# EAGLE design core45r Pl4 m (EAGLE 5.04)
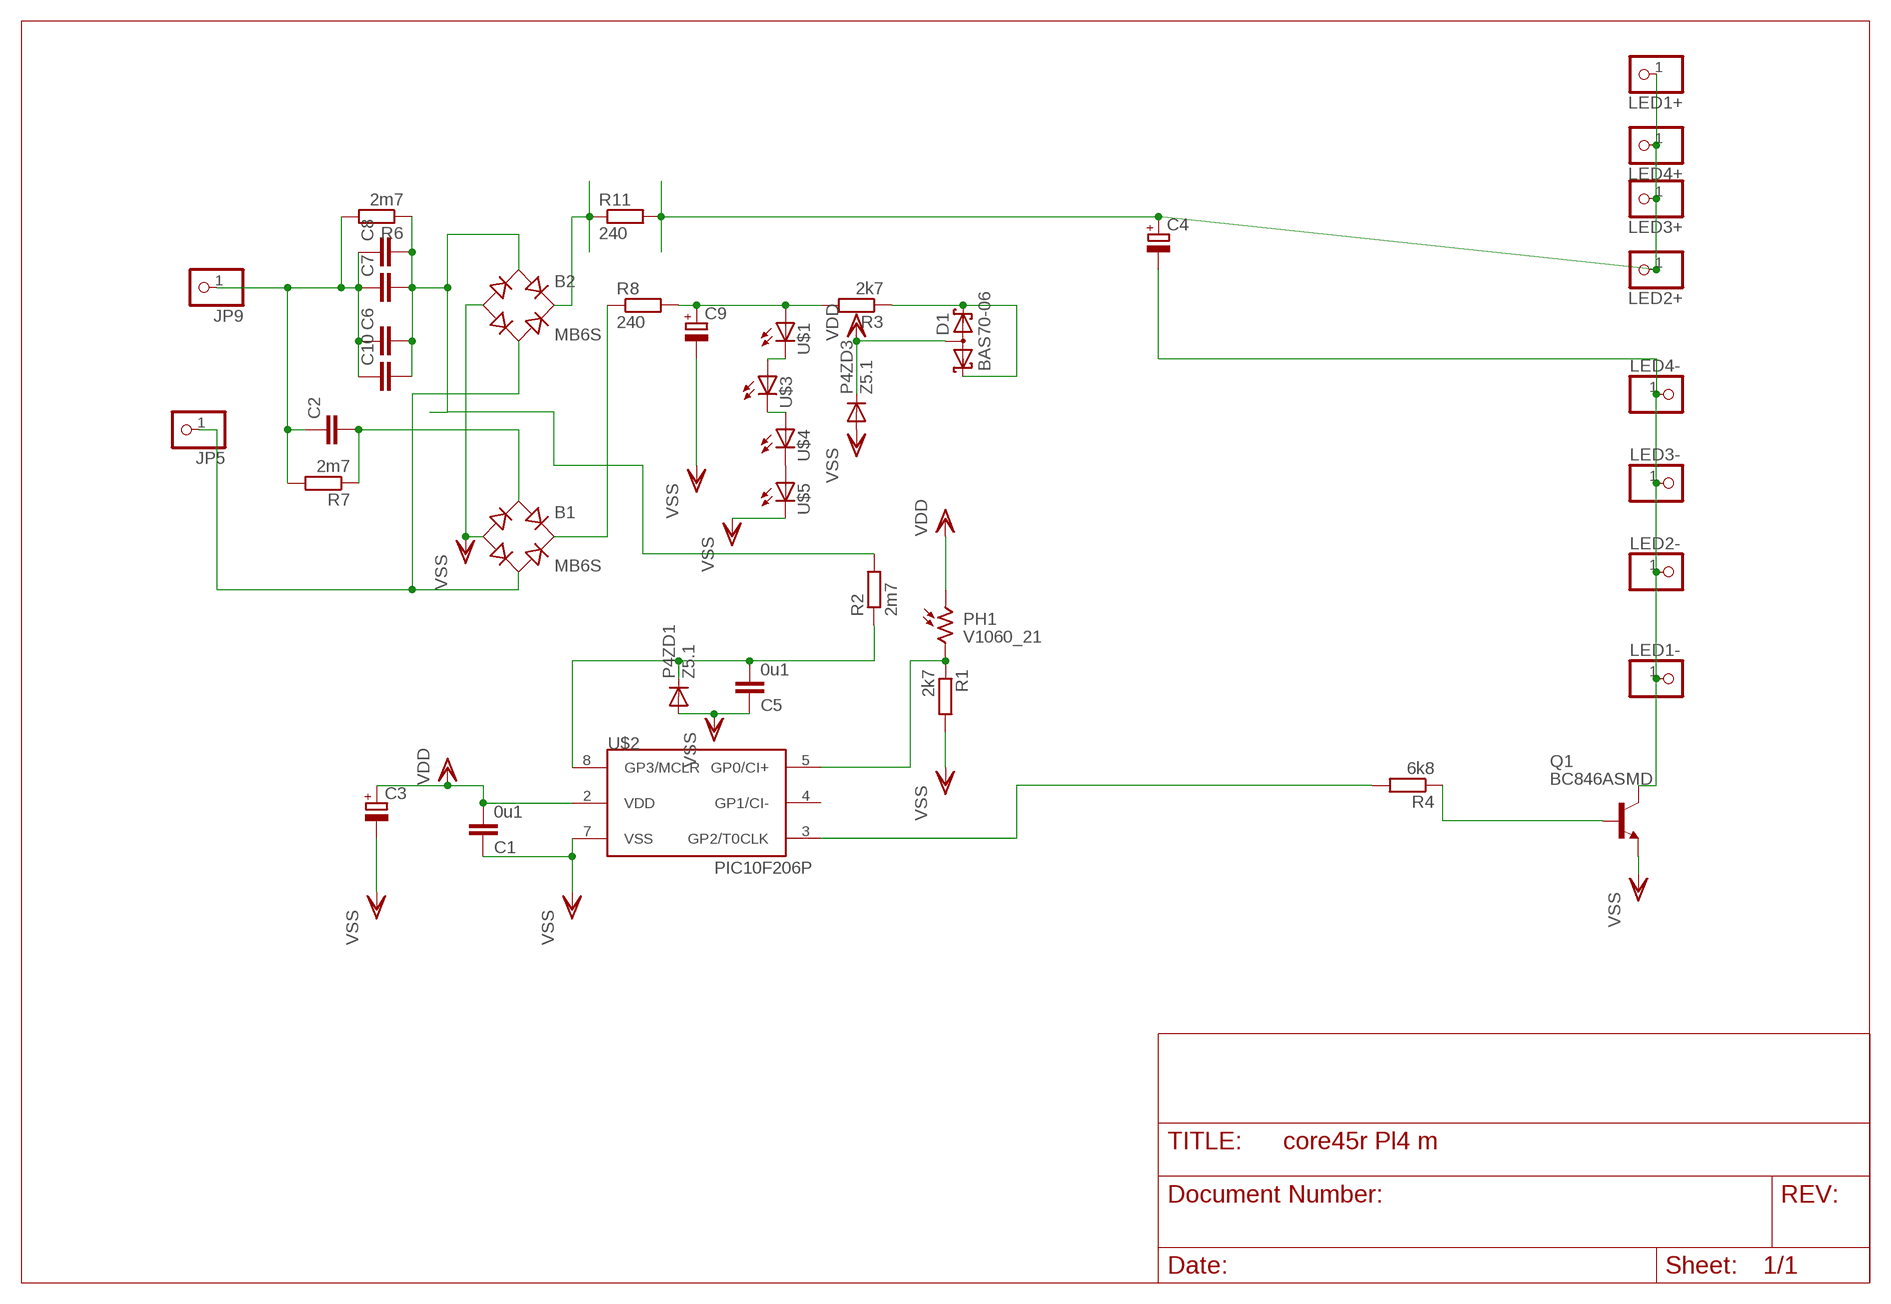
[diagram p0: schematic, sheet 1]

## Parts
B1  MB6S  [SOIC-4]
B2  MB6S  [SOIC-4]
C1  0u1  C-EUC1206  [C1206]
C2  C-EU075-052X106  [C075-052X106]
C3  CPOL-EU5-13  [2,5-5-FLAT]
C4  CPOL-EUTT5D11L  [TT5D11L]
C5  0u1  C-EUC1206  [C1206]
C6  C-EU150-064X183  [C150-064X183]
C7  C-EU150-054X183  [C150-054X183]
C8  C-EU150-054X183  [C150-054X183]
C9  CPOL-EUTT5D11L  [TT5D11L]
C10  C-EU150-064X183  [C150-064X183]
D1  BAS70-06  [SOT23]
JP5  PINHD-1X1  [1X01]
JP9  PINHD-1X1  [1X01]
LED1+  PINHD-1X1  [1X01]
LED1-  PINHD-1X1  [1X01]
LED2+  PINHD-1X1  [1X01]
LED2-  PINHD-1X1  [1X01]
LED3+  PINHD-1X1  [1X01]
LED3-  PINHD-1X1  [1X01]
LED4+  PINHD-1X1  [1X01]
LED4-  PINHD-1X1  [1X01]
P4ZD1  Z5.1  DIODE-MINIMELF  [MINIMELF]
P4ZD3  Z5.1  DIODE-MINIMELF  [MINIMELF]
PH1  V1060_21  [TO-5_V10]
Q1  BC846ASMD  [SOT23]
R1  2k7  R-EU_R0805  [R0805]
R2  2m7  R-EU_R1206  [R1206]
R3  2k7  R-EU_R0805  [R0805]
R4  6k8  R-EU_R1206  [R1206]
R6  2m7  R-EU_R1206  [R1206]
R7  2m7  R-EU_R1206  [R1206]
R8  240  R-EU_0204/5  [0204/5]
R11  240  R-EU_0204/7  [0204/7]
U$1  LED  [P-LCC4-MINI]
U$2  PIC10F206P  [DIL8]
U$3  LED  [P-LCC4-MINI]
U$4  LED  [P-LCC4-MINI]
U$5  LED  [P-LCC4-MINI]

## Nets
AC1: B1.~2(AC2) B2.~2(AC2) JP5.1
AC2: C2.1 C6.1 C7.1 C8.1 C10.1 JP9.1 R6.2 R7.2
CBIG: B2.~1(AC1) C6.2 C7.2 C8.2 C10.2 R2.2 R6.1
D+: C4.+ LED1+.1 LED2+.1 LED3+.1 LED4+.1 R11.2
D-: C4.- LED1-.1 LED2-.1 LED3-.1 LED4-.1 Q1.3(C)
DR+: C9.+ R3.2 R8.2 U$1.P$3(A)
N$1: C5.2 P4ZD1.C R2.1 U$2.8(GP3/MCLR)
N$2: U$4.P$1(C) U$5.P$3(A)
N$4: U$3.P$1(C) U$4.P$3(A)
N$5: D1.1(K1) D1.2(K2) R3.1
N$8: B1.~1(AC1) C2.2 R7.1
N$9: U$1.P$1(C) U$3.P$3(A)
N$11: B2.+ R11.1
N$12: Q1.1(B) R4.1
N$15: R4.2 U$2.3(GP2/T0CLK)
N$17: PH1.2 R1.1 U$2.5(GP0/CI+)
RECDR+: B1.+ R8.1
VDD: C1.2 C3.+ D1.3(AA) P4ZD3.C PH1.1 U$2.2(VDD)
VSS: B1.- B2.- C1.1 C3.- C5.1 C9.- P4ZD1.A P4ZD3.A Q1.2(E) R1.2 U$2.7(VSS) U$5.P$1(C)
Unconnected: U$2.4(GP1/CI-)

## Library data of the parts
B1 B2 = rectifier:MB*S: Bridge Rectifier Source: http://www.fairchildsemi.com/ds/MB/MB6S.pdf
C1 C5 = rcl:C-EU: CAPACITOR, European symbol
C2 C6-C8 C10 = rcl-2:C-EU: CAPACITOR, European symbol
C3 C4 C9 = rcl-2:CPOL-EU: POLARIZED CAPACITOR, European symbol
D1 = diode:BAS70-06: Silicon Schottky Diodes General-purpose diode for high-speed switching
JP5 JP9 LED1+ LED1- LED2+ LED2- LED3+ LED3- LED4+ LED4- = pinhead(2):PINHD-1X1: PIN HEADER
P4ZD1 P4ZD3 = diode:DIODE-: DIODE
PH1 = photo-elements:?1060*: Sensor Street Light control
Q1 = transistor-npn:BC846*: NPN Transistor
R1-R4 R6-R8 R11 = rcl-2:R-EU_: RESISTOR, European symbol
U$1 U$3-U$5 = led(2):LED: LED
U$2 = microchip-3:PIC10F2*: uPC nW 0,25/0,5k Program Flash memory Comparator

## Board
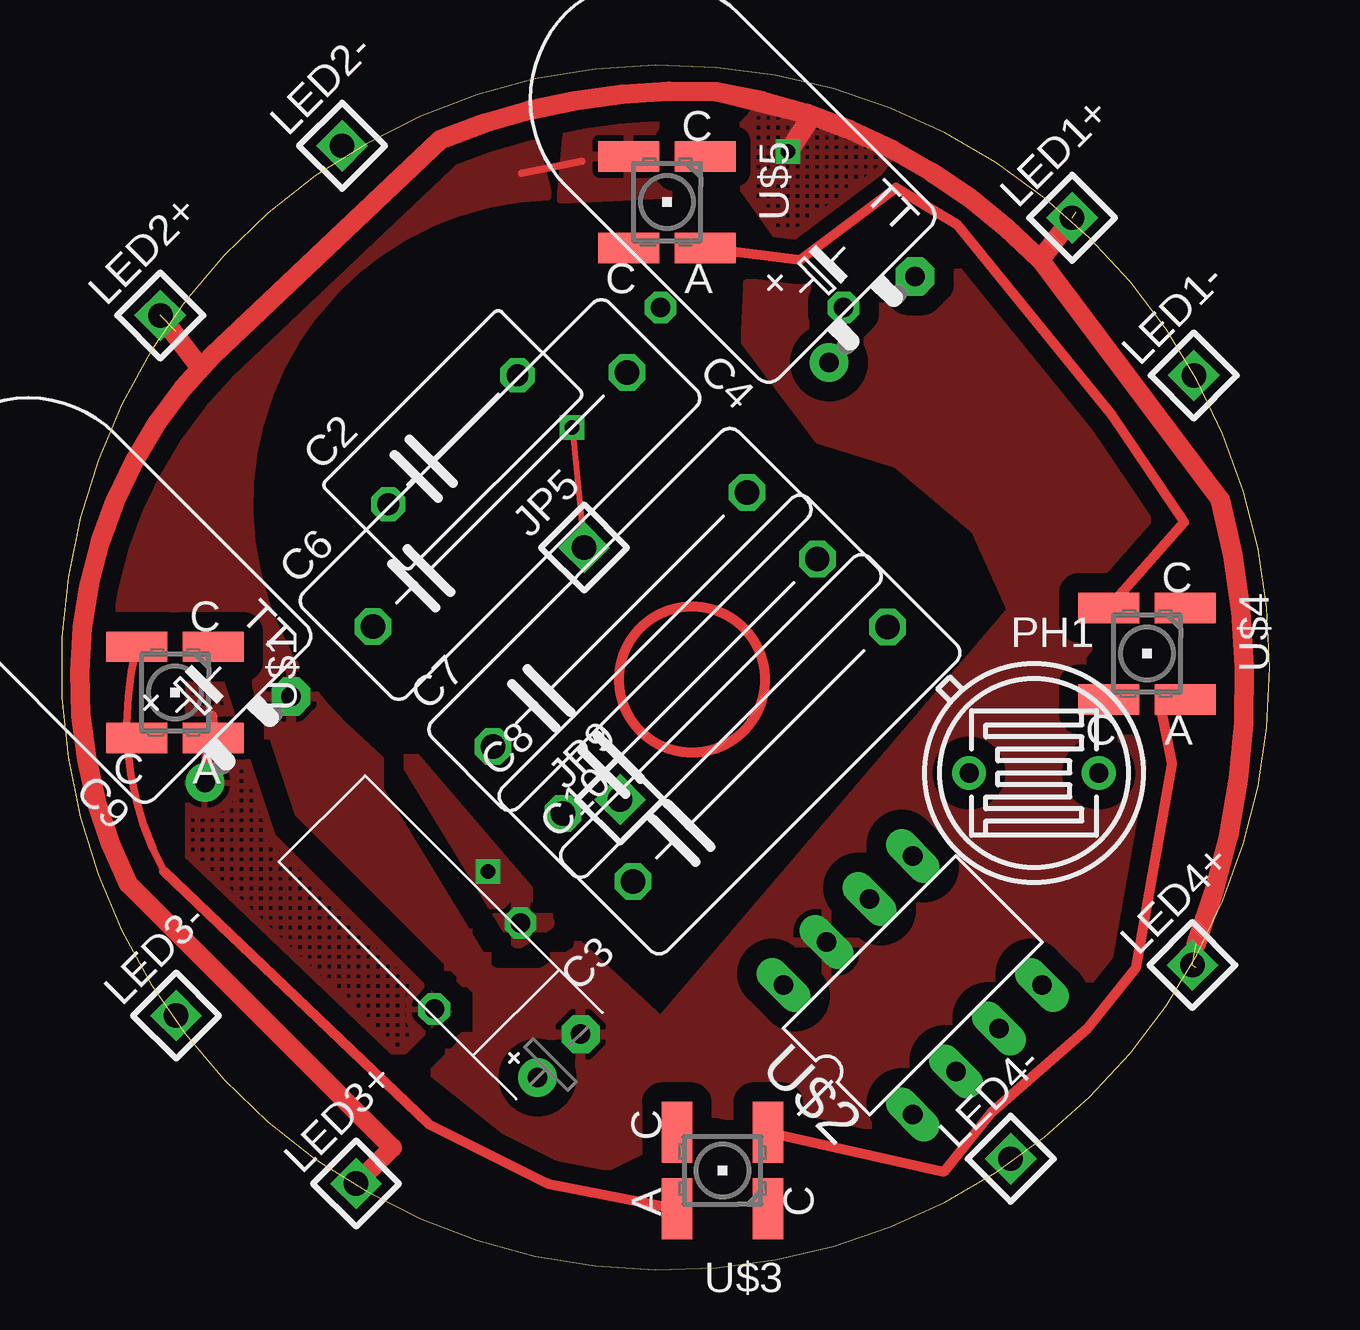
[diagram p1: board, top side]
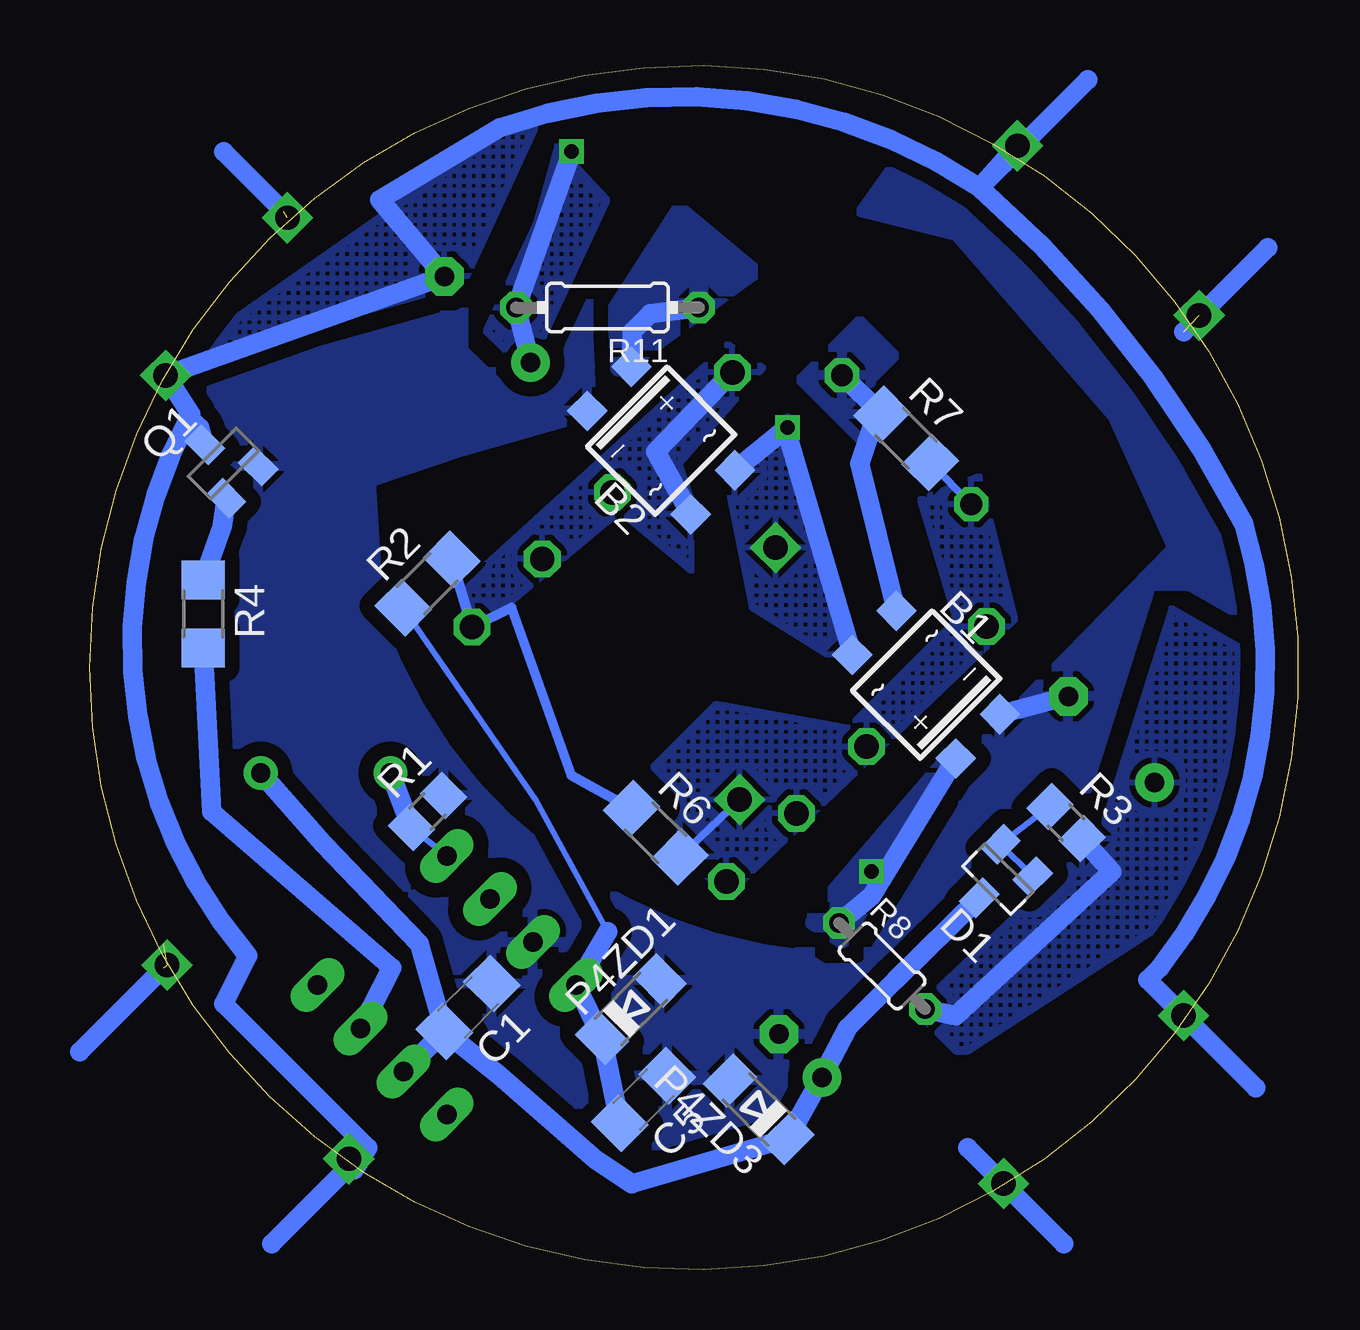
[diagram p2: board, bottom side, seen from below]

Size 50.33 x 50.19 mm. Coordinates in mm from the lower left corner, seen from the top.
Outline: 27.25,0.09 arc171 27.25,50.09 arc190 27.25,0.09
Copper layers (1*16): Top 0.035mm / dielectric 1.5mm / Bottom 0.035mm
Design rules "default": minimum track width 10mil, minimum drill 24mil, track to track 8mil, track to pad 8mil, pad to pad 8mil, via to via 8mil, smd to smd 8mil, copper to edge 40mil, drill to drill 8mil, minimum pad ring 10mil, minimum via ring 8mil, stop-mask expansion 4mil, vias tented up to drill 0mil, thermal gap 10mil

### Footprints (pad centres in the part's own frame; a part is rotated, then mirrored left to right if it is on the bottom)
SOIC-4 = smd 1.2 x 1.2: + 1.3,3.05; - -1.3,3.05; ~1 -1.3,-3.05; ~2 1.3,-3.05
C1206 = smd 1.6 x 1.8: 1 -1.4,0; 2 1.4,0
C075-052X106 = drill 0.914 octagon: 1 -3.81,0; 2 3.81,0
2,5-5-FLAT = drill 0.813 pad 1.6 round: + -1.27,0 | drill 0.813 pad 1.6 octagon: - 1.27,0
TT5D11L = drill 0.813 pad 1.6 round: + -2.54,0 | drill 0.813 pad 1.6 octagon: - 2.54,0
C150-064X183 = drill 1.016 octagon: 1 -7.493,0; 2 7.493,0
C150-054X183 = drill 1.016 octagon: 1 -7.493,0; 2 7.493,0
SOT23 = smd 1 x 1.4: 1 -0.95,-1.1; 2 0.95,-1.1; 3 0,1.1
1X01 = drill 1.016 square: 1 0,0
MINIMELF = smd 1.4 x 1.8: A 1.7,0; C -1.7,0
TO-5_V10 = drill 0.8 pad 1.4 round: 1 -2.7,0; 2 2.7,0
R0805 = smd 1.3 x 1.5: 1 -0.95,0; 2 0.95,0
R1206 = smd 1.6 x 1.803: 1 -1.422,0; 2 1.422,0
0204/5 = drill 0.813 octagon: 1 -2.54,0; 2 2.54,0
0204/7 = drill 0.813 octagon: 1 -3.81,0; 2 3.81,0
P-LCC4-MINI = smd 2.54 x 1.27: P$1 1.587,-1.905; P$2 -1.587,-1.905; P$3 -1.587,1.905; P$4 1.587,1.905
DIL8 = drill 0.813 long: 1 -3.81,-3.81; 2 -1.27,-3.81; 3 1.27,-3.81; 4 3.81,-3.81; 5 3.81,3.81; 6 1.27,3.81; 7 -1.27,3.81; 8 -3.81,3.81

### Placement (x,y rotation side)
B1  15.48,24.38 225 bottom
B2  26.52,34.55 45 bottom
C1  34.56,10.93 225 bottom
C2  16.29,34.58 45 top
C3  20.72,8.92 45 top
C4  33.75,39.59 45 top
C5  27.25,7.09 225 bottom
C6  18.25,32.09 45 top
C7  23.25,27.09 45 top
C8  26.17,24.32 45 top
C9  7.75,22.09 45 top
C10  29.1,21.48 45 top
D1  12.48,16.28 135 bottom
JP5  21.75,30.09 45 top
JP9  23.25,19.59 45 top
LED1+  42.09,43.83 45 top
LED1-  47.16,37.26 45 top
LED2+  4.1,39.76 45 top
LED2-  11.67,46.83 45 top
LED3+  12.25,3.59 45 top
LED3-  4.75,10.59 45 top
LED4+  47.1,12.69 45 top
LED4-  39.53,4.62 45 top
P4ZD1  27.78,10.86 45 bottom
P4ZD3  22.45,6.68 135 bottom
PH1  40.5,20.7 180 top
Q1  44.75,33.59 45 bottom
R1  36.25,19.09 45 bottom
R2  36.25,28.59 45 bottom
R3  9.65,18.63 315 bottom
R4  45.59,27.32 270 bottom
R6  26.75,18.21 315 bottom
R7  16.31,34.64 315 bottom
R8  17.31,12.66 315 bottom
R11  28.75,40.09 180 bottom
U$1  4.71,24.05 180 top
U$2  35.45,11.86 45 top
U$3  27.52,4.13 90 top
U$4  45.21,25.67 180 top
U$5  25.21,44.48 180 top

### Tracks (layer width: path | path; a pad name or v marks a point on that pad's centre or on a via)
AC1  (via drill 0.6)
  Top 0.254: v21.25,35.09 JP5.1
  Bottom 0.254: 21.32,35.05 v21.25,35.09
  Bottom 0.813: B1.~2 21.32,35.05 B2.~2
  pour Bottom (isolate 0.61, hatched): 21.25,35.59 23.75,32.59 22.75,27.59 18.75,25.09
AC2
  Bottom 0.305: R6.2 JP9.1 | C2.1 R7.2
  pour Bottom (isolate 0.813, rank 2, hatched): 13.25,33.09 15.75,32.09 14.25,27.09 18.75,22.59 24.25,23.59 28.25,19.59 23.75,15.59 11.75,27.09
CBIG
  Bottom 0.406: R6.1 30.25,20.59 32.75,27.59 C10.2 R2.2
  Bottom 0.813: B2.~1 26.75,34.09 C6.2
  pour Bottom (isolate 0.61, hatched): 23.75,38.59 34.75,28.59 34.25,26.59 28.25,31.59 25.25,29.09 25.25,32.09 25.75,33.59 22.25,37.59
D+  (via drill 0.6)  (4 unrouted)
  Top 0.406: 6.25,38.09 5.75,37.59
  Top 0.813: 5.75,37.59 LED2+.1 | LED3+.1 13.75,5.09 2.75,16.09 arc-71 6.25,38.09 15.75,47.09 arc-25 27.25,49.09 | 47.25,13.59 arc36 48.25,32.09 40.75,42.09 | 40.75,42.09 LED1+.1 | 27.25,49.09 arc-37 40.75,42.09 | v30.25,46.59 31.25,48.09 27.25,49.09
  Bottom 0.813: C4.+ R11.2 v30.25,46.59 | 42.25,44.09 44.75,46.59 | 47.25,12.59 50.75,9.09 | 1.25,42.59 4.75,39.09
  pour Bottom (isolate 0.406, hatched): 30.85,46.84 31.75,43.59 33.85,39.09 32.1,37.39 28.75,44.59
  pour Top (isolate 0.61, hatched): 29.35,48.84 34.75,46.59 32.35,43.59 30.6,41.89 27.25,46.59
D-
  Bottom 0.813: 13.25,45.09 arc-53 33.25,47.59 38.25,44.59 C4.- LED1-.1 46.11,35.65 | 13.25,45.09 arc21 2.25,31.09 arc56 5.75,12.59 6.25,12.09 5.25,11.09 | 5.25,11.09 LED3-.1 | 39.3,4.16 38.75,5.09 44.75,11.09 43.75,13.09 arc69 46.11,35.65 | 39.3,4.16 LED4-.1 | 11.75,46.59 8.75,49.59 | 11.75,46.59 12.25,46.09 | 1.75,7.59 5.25,11.09 | 42.75,1.09 39.25,4.59 39.3,4.16 | 13.25,45.09 LED2-.1 | 13.25,45.09 11.75,46.59 | 46.11,35.65 46.25,35.59 45.75,35.09 Q1.3
  pour Bottom (isolate 0.406, rank 2, hatched): 32.25,48.09 47.25,37.59 34.75,41.09 31.75,47.59
DR+
  Top 0.406: C9.+ 6.25,23.09 U$1.P$3
  Bottom 0.813: R3.2 7.75,16.59 14.25,10.59 R8.2
  pour Bottom (isolate 0.61, hatched): 1.75,25.59 5.25,27.59 8.25,18.09 16.25,10.59 15.75,10.59 14.25,9.09 13.75,9.09 3.75,15.59
  pour Top (isolate 0.813, hatched): 5.25,25.59 3.75,28.09 5.75,27.59 5.75,27.09 8.75,18.09 16.25,10.59 15.75,10.59 14.25,9.09 13.75,9.09 5.25,17.09
N$1
  Bottom 0.254: R2.1 31.75,19.59 28.75,14.09
  Bottom 0.813: 28.75,14.09 U$2.8 P4ZD1.C C5.2
N$2
  Top 0.406: U$4.P$1 46.75,31.14 43.75,35.59 37.25,43.59 34.75,45.09 30.75,42.09 U$5.P$3
N$4
  Top 0.406: U$3.P$1 36.75,4.09 38.75,6.59 42.75,10.09 44.75,12.59 46.25,21.09 45.75,23.59 U$4.P$3
N$5
  Bottom 0.254: R3.1 D1.2 D1.1
N$8
  Bottom 0.813: C2.2 R7.1 17.75,35.09 18.25,33.59 B1.~1
  pour Bottom (isolate 0.61): 17.75,37.09 16.75,38.09 18.25,39.59 20.75,37.09 18.25,34.59
N$9
  Top 0.305: 4.25,16.59 arc-43 U$1.P$1
  Top 0.406: 4.25,16.59 15.25,6.09 20.25,3.59 U$3.P$3
N$10
  Bottom 0.813: 9.75,1.09 13.75,5.09
N$11
  Bottom 0.813: B2.+ 27.72,39.09 26.97,39.84 R11.1
  pour Bottom: 28.25,37.59 28.35,40.04 25.75,44.09 22.75,41.59
N$12
  Bottom 0.813: Q1.1 44.8,30.98 R4.1
N$15
  Bottom 0.813: U$2.3 37.75,12.59 45.25,19.09 R4.2
N$17
  Bottom 0.254: U$2.5 R1.1
  Bottom 0.813: R1.1 PH1.2
RECDR+  (via drill 0.6)
  Bottom 0.813: B1.+ 17.75,15.59 R8.1
  other vias: 17.75,16.59
  pour Bottom (isolate 0.61): 14.25,21.59 19,13.79 20.25,14.59
  pour Top (isolate 0.61): 14.25,21.59 19,13.79 20.25,14.59
VDD
  Bottom 0.813: C1.2 33.25,8.09 29.25,4.59 27.75,3.59 P4ZD3.C C3.+ 18.75,10.09 16.75,12.09 D1.3 | C1.2 36.6,13.59 40.6,17.74 PH1.1 | C1.2 U$2.2
VSS
  Top 0.305: 19.15,45.69 21.65,46.19
  Bottom 0.813: C9.- B1.-
  pour Bottom (isolate 0.61, rank 5): -0.15,24.51 1.59,34.75 16.71,46.25 18.25,44.09 14.25,43.09 7.75,35.59 5.25,30.09 21.12,13.84 20.25,13.09 arc66 38.25,27.09 38.59,32.81 34.79,34.11 29.54,35.61 26.98,38.17 23.48,40.8 17.12,47.16 18.25,48.09 20.62,50.78 27.78,49.94 35.48,48.94 arc-55 49.91,25.01 47.41,15.8 36.19,3.52 22.63,0.72 arc-64
  pour Top (isolate 0.813, rank 5): -1.5,21.81 arc-76 19.59,47.25 20.21,44.75 arc135 11.75,22.59 24.95,10.34 39.59,27.48 38.09,30.81 34.79,33.61 31.54,34.61 28.48,38.67 28.78,45 20.82,44.61 21.12,47.78 24.28,50.44 41.98,42.44 arc-85 42.41,25.51 48.31,15.7 36.24,4.62 27.28,6.52 21.25,3.59
(copper drawn outside any net)
  shapes: Top circle x1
